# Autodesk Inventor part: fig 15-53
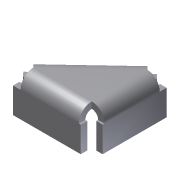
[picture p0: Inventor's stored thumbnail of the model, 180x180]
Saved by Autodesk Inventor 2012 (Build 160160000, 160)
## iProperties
Created: 2008-06
Part Number: fig 15-53
Material: Default
Document SubType Name: Sheet Metal
Designer: CADCIM
Density: 1 g/cm^3
Sheet Metal Rule: Default_mm
Author: CADCIM
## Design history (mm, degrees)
node "Face1"
  sketch "Sketch1"
    geometry: L1 (10.277, 2.151)-(10.277, -5.485); L2 (10.277, -5.485)-(2.197, -5.485); L3 (10.277, 2.151)-(2.197, -5.485)
    constraints: 6 end point
node "Flange2"
body "Solid1"
face "Plate1" dims "Thickness" = 0.5
sketch "Sketch3"
  geometry: L1 (0, -3)-(7.636, -3); L2 (7.636, -3)-(7.636, 0); 2 other entities
  constraints: 4 end point, 4 other
face "Plate3" dims "d16" = 0.5 (= BendReliefWidth), "d17" = 0.25 (= BendReliefDepth), "d18" = 1 (= MinimumRemnant), "d19" = 0.5 (= BendRadius), "d20" = 3, "d21" = 90 deg, "d22" = 0.5 (= BendRadius), "d23" = 2 (= CornerReliefSize), "d24" = 0.5 (= Thickness), "d25" = 0.5 (= JacobiRadiusSize), "SeamGap" = 0.01, "Thickness" = 0.5
bend "Bend2" dims "d16" = 0.5 (= BendReliefWidth), "d17" = 0.25 (= BendReliefDepth), "d18" = 1 (= MinimumRemnant), "d19" = 0.5 (= BendRadius), "d20" = 3, "d21" = 90 deg, "d22" = 0.5 (= BendRadius), "SeamGap" = 0.01, "Thickness" = 0.5
feature "Corner2" dims "d20" = 3, "d21" = 90 deg, "d23" = 2 (= CornerReliefSize), "d24" = 0.5 (= Thickness), "d25" = 0.5 (= JacobiRadiusSize)
other parameters: "BendRadius" = 0.5 (= Thickness), "BendReliefWidth" = 0.5 (= Thickness), "BendReliefDepth" = 0.25 (= 0.5 x Thickness), "CornerReliefSize" = 2 (= 4 x Thickness), "MinimumRemnant" = 1 (= 2 x Thickness), "TransitionRadius" = 0.5 (= BendRadius), "JacobiRadiusSize" = 0.5 (= BendRadius), "d0" = 0.5 (= BendRadius), "GapSize" = 0.5 (= Thickness)
